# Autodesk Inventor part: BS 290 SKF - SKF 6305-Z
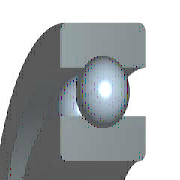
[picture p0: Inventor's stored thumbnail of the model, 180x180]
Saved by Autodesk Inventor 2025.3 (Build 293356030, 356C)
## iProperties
Created: 2024-01
Part Number: BS 290 SKF - SKF 6305-Z
Material: Acciaio, Dolce
Description: Cuscinetti a sfere con scanalatura profonda a fila singola con protezione Z SKF
Document SubType Name: Modeling
Standard: BS 290 SKF
Designer: R5800u
Standards Organization: BSI
Language: it-IT
Size Designation: SKF 6305-Z
Categories: <MemberInstance><Categories><Category DisplayName="Parti albero" InternalName="7f7aeb1f-a693-4053-b835-cee3144e0d98" Mnemonic="SHFT"><Category DisplayName="Cusc
Density: 7.85 g/cm^3
Appearance: Semilucidato
IsCustomPart: 0
Author: R5800u
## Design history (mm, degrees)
node "WorkPoint1"
node "WorkAxis1"
node "WorkPlane3"
node "WorkPlane4"
node "WorkPoint2"
pattern_circular "Seriepolare1" dims "d17" = 62.78378 (= msp_pocet), angle "d19" = 360 deg
body "Solid1"
node "Schizzo1"
revolve "Rivoluzione1" stored, may be unused: angle "d6" = 360 deg
revolve "Rivoluzione2" stored, may be unused: angle "d10" = 360 deg
node "Schizzo4"
revolve "Rivoluzione3" stored, may be unused: angle "d16" = 360 deg
fillet "Raccordo1" dims "d20" = 1.1 (= r)
sketch "Schizzo2"
  geometry: L1 (12.5, 17)-(31, 17); L2 (12.5, 0)-(12.5, 17); L3 (31, 0)-(12.5, 0); L4 (31, 17)-(31, 0); L5 (0, 0)-(0, 20); L6 (0, 0)-(0, 20); L7 (-7.2, 0)-(43.2, 0) reference
  constraints: 12 end point, 3 vertical, 2 horizontal, 1 collinear, 1 other
  dimensions: "d1" = 25 diameter of L1.start L5 (= Diam); "d3" = 62 diameter of L1.end L5 (= DD); "d5" = 17 distance of L2.start L1.start (= msp_mdtd2)
sketch "Schizzo3"
  geometry: L1 (25.08, 17)-(25.08, 12.94); L2 (18.42, 17)-(25.08, 17); L3 (18.42, 12.94)-(18.42, 17); L4 (18.42, 0)-(18.42, 4.06); L5 (25.08, 0)-(18.42, 0); L6 (25.08, 4.06)-(25.08, 0); L7 (31, 0)-(-31, 0) reference; L8 (31, 17)-(-31, 17) reference; L9 (0, -42.29)-(0, 61.29); L10 (0, 82.007)-(0, -63.007) reference; A1 r 5.55 centre (21.75, 8.5) between (25.08, 4.06) and (25.08, 12.94); A2 r 5.55 centre (21.75, 8.5) between (18.42, 12.94) and (18.42, 4.06)
  constraints: 14 end point, 4 collinear, 4 point on circle, 4 vertical, 2 centre point, 2 concentric, 2 horizontal, 2 point on line
  dimensions: "d9" = 11.1 diameter of A1 (= msp_mdtd6); "d21" = 18.42 distance between parallel lines of L9 L4 (= 0.5 x msp_d1); "d22" = 21.75 distance from line of L9 A1.centre (= 0.5 x msp_ds); "d23" = 25.08 distance between parallel lines of L9 L6 (= 0.5 x msp_dd1)
sketch "Schizzo5"
  geometry: L1 (21.75, 2.95)-(21.75, 14.05); L2 (25.08, 0)-(-25.08, 0) reference; L3 (21.75, 2.95)-(21.75, 14.05); A1 r 5.55 centre (21.75, 8.5) between (21.75, 2.95) and (21.75, 14.05); A2 r 5.55 centre (21.75, 8.5) between (25.08, 4.06) and (25.08, 12.94) reference
  constraints: 4 end point, 2 point on circle, 1 centre point, 1 concentric, 1 vertical
  dimensions: "d13" = 0 horizontal distance of A1.centre L1.start; "d15" = 11.1001 diameter of A1 (computed from msp_mdtd6)
other parameters: "Diam" = 25 [user parameter; used in 3 equation terms], "DD" = 62 [user parameter; used in 3 equation terms], "B" = 17 [user parameter; used in 1 equation term], "r" = 1.1 [user parameter; used in 1 equation term], "msp_ds" = 43.5 (= 0.5 x Diam + 0.5 x DD) [user parameter; used in 5 equation terms], "msp_d0" = 11.1 (= -0.3 x Diam + 0.3 x DD) [user parameter; used in 4 equation terms], "msp_d1" = 36.84 (= msp_ds - 0.6 x msp_d0) [user parameter; used in 1 equation term], "msp_dd1" = 50.16 (= msp_ds + 0.6 x msp_d0) [user parameter; used in 1 equation term], "msp_pom" = 65.25 (= 1.5 x msp_ds) [user parameter; used in 1 equation term], "msp_mdtd2" = 17 (= B) [user parameter; used in 3 equation terms], "msp_mdtd4" = 43.5 (= msp_ds) [user parameter], "msp_mdtd6" = 11.1 (= msp_d0) [user parameter; used in 2 equation terms], "msp_mdtd7" = 8.5 (= 0.5 x msp_mdtd2) [user parameter], "msp_pocet" = 62.78378 (computed from msp_d0, msp_pom) [user parameter; used in 1 equation term], "d2" = 72 (derived), "d4" = 19 (derived), "d7" = 0, "d8" = 15.6 (derived), "d11" = -17 (computed from msp_mdtd2), "d12" = 0 (derived), "d14" = 15.6001 (derived), "d26" = 0, "d27" = 0, "d28" = 0, "d29" = 0, "d30" = 0
